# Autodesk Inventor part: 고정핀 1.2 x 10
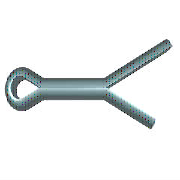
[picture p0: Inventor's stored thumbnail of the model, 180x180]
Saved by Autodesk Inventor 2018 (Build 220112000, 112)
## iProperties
IsCustomPart: 1
Created: 2012-02
Part Number: 고정핀 1.2 x 10
Material: 강철
Description: 분할 핀
Document SubType Name: Modeling
Standard: ISO 1234
Designer: test
Standard Revision: Second edition 1997-11-01
Standards Organization: ISO
Language: ko-KR
Size Designation: 1.2 x 10
Categories: <MemberInstance><Categories><Category DisplayName="조임쇠" InternalName="e4da775c-781d-43d5-af7c-5136215cf5a6" Mnemonic="FSTN"><Category DisplayName="핀" InternalNa
Density: 7.85 g/cm^3
Appearance: 파란색 - 벽 페인트 - 광택
Author: test
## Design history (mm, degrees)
sketch "스케치1"
  geometry: L1 (0, 0.5)-(5, 0.5); L2 (0, -0.5)-(5, -0.5); L3 (5, 0.5)-(10, 2.416); L4 (10, 2.416)-(10.167, 1.98); L5 (10.167, 1.98)-(5, 0); L6 (5, 0)-(12.667, -2.937); L7 (12.667, -2.937)-(12.5, -3.373); L8 (12.5, -3.373)-(5, -0.5); L9 (0, 0)-(-1.875, -0.484); L10 (0, 0)-(-1.875, 0.484); L11 (0, 0.5)-(0, -0.5); L12 (0, 0.5)-(-1.742, 0.966); L13 (0, -0.5)-(-1.742, -0.966); L14 (-3, 0)-(5, 0); L15 (5, 0.5)-(5, -0.5); A1 r 1 centre (-2, 0) between (-1.742, 0.966) and (-1.742, -0.966); A2 r 0.5 centre (-2, 0) between (-1.875, 0.484) and (-1.875, -0.484); 1 further point
  constraints: 30 end point, 5 point on circle, 4 parallel, 4 perpendicular, 4 point on line, 4 tangent, 2 centre point, 2 midpoint, 1 coincident, 1 horizontal
  dimensions: "d0" = 5 distance of L1.start L1.end (= MSIAB); "d1" = 10 horizontal distance of L1.start L3.end (= SNLG); "d2" = 159.037 deg angle of L1 L3; "d3" = 159.037 deg angle of L2 L8; "d4" = 2.5 horizontal distance of L3.end L7.end (= LGDIF); "d5" = 0.5 radius of A2 (= -0.5 x SNND1 + 0.5 x KBR); "d6" = 1 radius of A1 (= 0.5 x KBR); "d7" = 0.5 distance from line of L1 L9.start (= 0.5 x SNND1); "d8" = 0.5 distance between parallel lines of L2 L14 (= 0.5 x SNND1); "d9" = 2 distance from line of L11 A1.centre (= KOL - 0.5 x KBR)
extrude "본체" new body sketch "스케치1" stored distance "d10" = 1 (= SNND1); taper "d11" = 0 deg
workaxis "Work Axis1"
workplane "Work Plane1"
workplane "Work Plane3"
body "Solid1"
fillet "모깎기" dims "d12" = 0.35 (= 0.35 x SNND1)
other parameters: "SNND" = 1.2 [user parameter], "SNLG" = 10 [user parameter; used in 1 equation term], "SNND1" = 1 [user parameter; used in 5 equation terms], "KBR" = 2 [user parameter; used in 3 equation terms], "KOL" = 3 [user parameter; used in 1 equation term], "LGDIF" = 2.5 [user parameter; used in 1 equation term], "MSIAB" = 5 [user parameter; used in 1 equation term], "d15" = 0, "d16" = 0, "d17" = 0, "NNDMAX" = 5.5 [user parameter], "DSH" = 2.6 [user parameter], "NNDMIN" = 4.5 [user parameter]
